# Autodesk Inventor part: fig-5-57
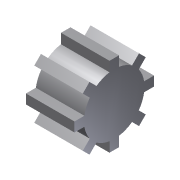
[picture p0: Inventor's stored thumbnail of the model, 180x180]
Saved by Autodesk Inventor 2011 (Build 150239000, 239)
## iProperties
Created: 2005-12
Part Number: fig-5-57
Document SubType Name: Modeling
Designer: CADCIM
Density: 1 g/cm^3
Author: CADCIM
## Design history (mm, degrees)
sketch "Sketch1"
  geometry: C1 r 27.506 at (0, 0)
  constraints: 1 centre point
extrude "Extrusion1" new body sketch "Sketch1" distance "d0" = 20; taper "d1" = 0 deg
sketch "Sketch2"
  geometry: L1 (-12.302, -1.705)-(-16.396, -1.705); L2 (-16.396, -1.705)-(-16.396, 2.216); L3 (-16.396, 2.216)-(-12.302, 2.216); L4 (-7.311, -9.833)-(-10.206, -12.728); L5 (-10.206, -12.728)-(-12.979, -9.955); L6 (-12.979, -9.955)-(-10.084, -7.06); L7 (1.966, -12.051)-(1.966, -16.145); L8 (1.966, -16.145)-(-1.956, -16.145); L9 (-1.956, -16.145)-(-1.956, -12.051); L10 (10.093, -7.06)-(12.988, -9.955); L11 (12.988, -9.955)-(10.215, -12.728); L12 (10.215, -12.728)-(7.32, -9.833); L13 (12.311, 2.216)-(16.405, 2.216); L14 (16.405, 2.216)-(16.405, -1.705); L15 (16.405, -1.705)-(12.311, -1.705); L16 (7.32, 10.344)-(10.215, 13.239); L17 (10.215, 13.239)-(12.988, 10.466); L18 (12.988, 10.466)-(10.093, 7.571); L19 (-1.956, 12.562)-(-1.956, 16.656); L20 (-1.956, 16.656)-(1.966, 16.656); L21 (1.966, 16.656)-(1.966, 12.562); L22 (-10.084, 7.571)-(-12.979, 10.466); L23 (-12.979, 10.466)-(-10.206, 13.239); L24 (-10.206, 13.239)-(-7.311, 10.344); A1 r 12.462 centre (0.005, 0.256) between (-12.302, -1.705) and (-10.084, -7.06); A2 r 12.462 centre (0.005, 0.256) between (-7.311, -9.833) and (-1.956, -12.051); A3 r 12.462 centre (0.005, 0.256) between (1.966, -12.051) and (7.32, -9.833); A4 r 12.462 centre (0.005, 0.256) between (10.093, -7.06) and (12.311, -1.705); A5 r 12.462 centre (0.005, 0.256) between (12.311, 2.216) and (10.093, 7.571); A6 r 12.462 centre (0.005, 0.256) between (7.32, 10.344) and (1.966, 12.562); A7 r 12.462 centre (0.005, 0.256) between (-1.956, 12.562) and (-7.311, 10.344); A8 r 12.462 centre (0.005, 0.256) between (-10.084, 7.571) and (-12.302, 2.216)
  constraints: 48 end point, 16 point on circle, 8 centre point, 2 parallel, 1 horizontal, 1 perpendicular, 57 other
  dimensions: "d4" = 360 deg dimension on A1.centre L2.end (derived)
extrude "Extrusion2" sketch "Sketch2" distance "d6" = 20; taper "d7" = 0 deg
body "Solid1"
